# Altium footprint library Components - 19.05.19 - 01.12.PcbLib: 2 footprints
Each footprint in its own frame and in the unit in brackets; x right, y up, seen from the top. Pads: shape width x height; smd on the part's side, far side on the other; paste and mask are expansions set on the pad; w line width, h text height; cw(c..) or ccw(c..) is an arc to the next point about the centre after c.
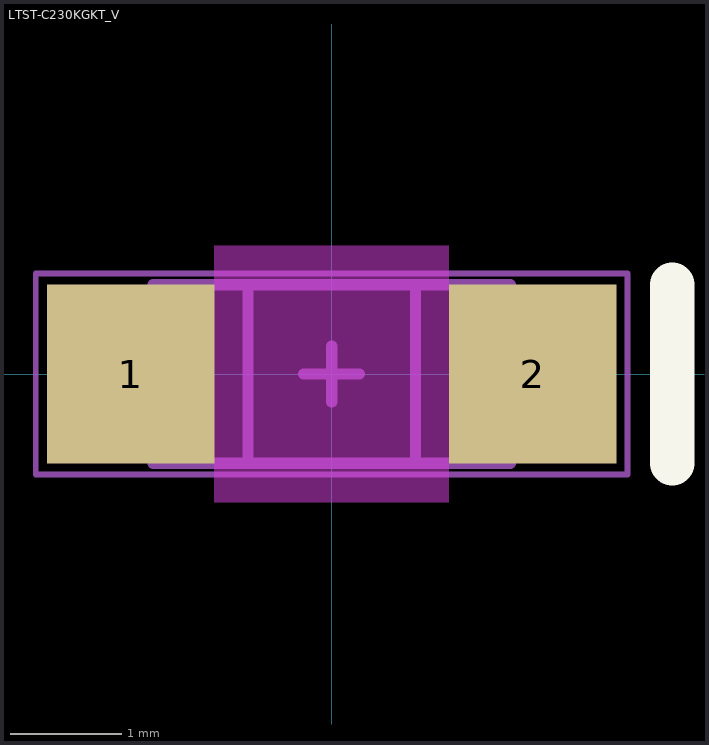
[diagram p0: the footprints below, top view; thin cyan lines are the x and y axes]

## LTST-C230KGKT_V [mm] "SMD, 2-Leads, Body 3.2x1.6mm"
height 0.38
pads (2):
  rect 1.5x1.6 smd: 1(-1.8,0) 2(1.8,0)
Top Overlay:
  lines w0.4: 3.05,-0.8 3.05,0.8
Keep-Out Layer:
  board cut-out: -1.05,1.15 1.05,1.15 1.05,-1.15 -1.05,-1.15
Mechanical 13:
  lines w0.1: -0.75,-0.8 -0.75,0.8 ; 0.75,-0.8 0.75,0.8 ; -1.6,-0.8 -1.6,0.8 1.6,0.8 1.6,-0.8 -1.6,-0.8
Mechanical 15:
  lines w0.05: -2.65,-0.9 -2.65,0.9 2.65,0.9 2.65,-0.9 -2.65,-0.9
  lines w0.1: -0.25,0 0.25,0 ; 0,-0.25 0,0.25
3D body: height 0.38, standoff 0, extent -1.6,-0.8 1.6,0.8
3D body: height 0, standoff -0.82, extent -0.75,-0.8 0.75,0.8

## PCBComponent_1 [mm]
